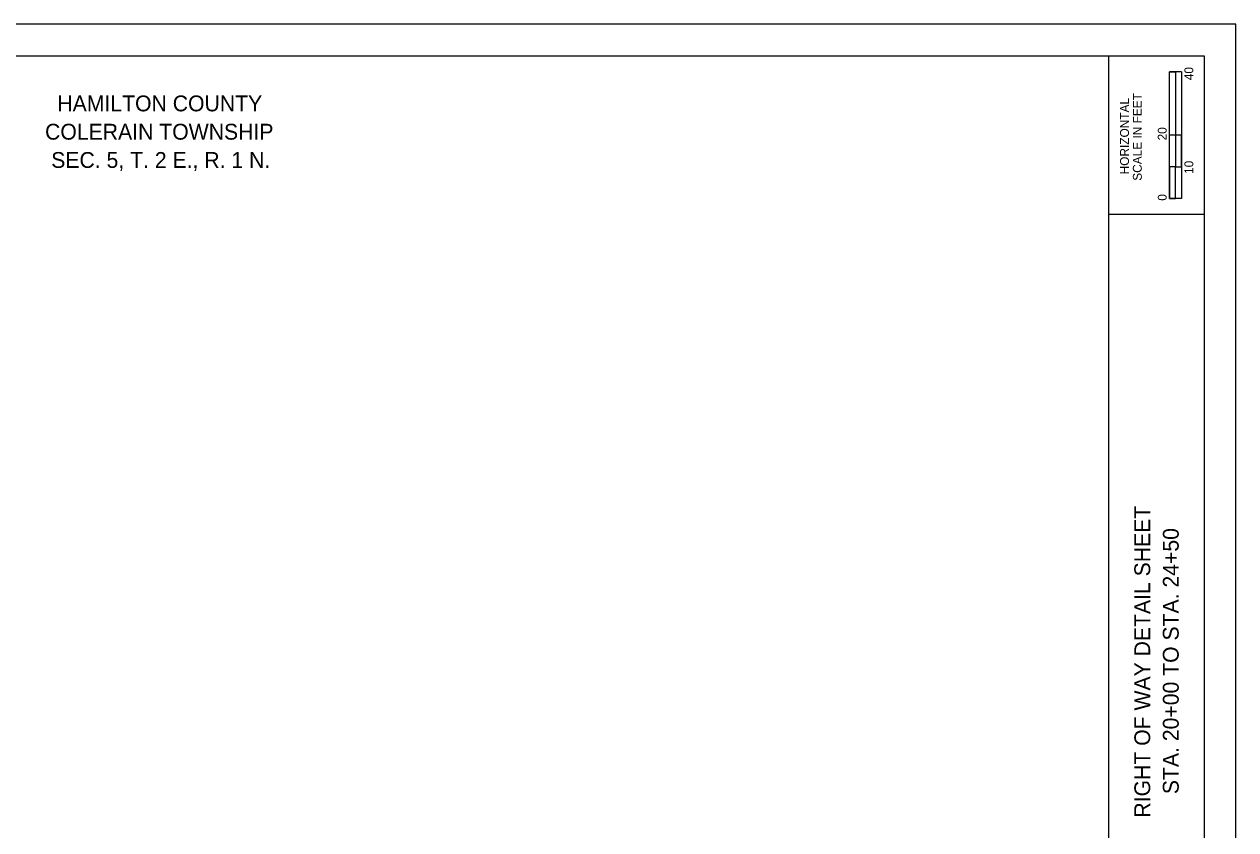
# Model space of a CAD drawing. Extents: x -0.5 to 34, y 0 to 22.
# Drawn here: x 14.89 to 34, y 9.28 to 22 of the extents above; entities that cross this region are included whole.
import ezdxf

# ---------------------------------------------------------------- set-up
doc = ezdxf.new("R2010")
doc.units = 0
for name, color, linetype in [('SH_Border', 7, 'Continuous'), ('SH_Cut_Line', 7, 'Continuous'), ('SH_Data', 7, 'Continuous')]:
    doc.layers.add(name, color=color, linetype=linetype)

msp = doc.modelspace()

# ---------------------------------------------------------------- linework, layer by layer
at = {"layer": 'SH_Border'}
for p, q in [((32, 0.5), (32, 21.5)), ((32, 19), (33.5, 19))]:
    msp.add_line(p, q, dxfattribs=at)
msp.add_lwpolyline([(1.5, 21.5), (33.5, 21.5), (33.5, 0.5), (1.5, 0.5)], close=True, dxfattribs=at)
at = {"layer": 'SH_Cut_Line'}
msp.add_lwpolyline([(0, 0), (34, 0), (34, 22), (0, 22)], close=True, dxfattribs=at)
at = {"layer": 'SH_Data'}
for p, q in [((32.957, 19.25), (32.957, 21.25)), ((33.144, 21.25), (32.957, 21.25)), ((32.957, 20.25), (32.957, 21.25)), ((32.957, 21.25), (33.05, 21.25)), ((33.05, 21.25), (33.051, 21.25)), ((33.051, 21.25), (33.051, 20.25)), ((33.144, 21.25), (33.144, 19.25)), ((33.051, 20.25), (32.957, 20.25)), ((33.143, 20.25), (33.05, 20.25)), ((33.05, 20.25), (33.05, 19.75)), ((33.143, 19.75), (33.143, 20.25)), ((33.05, 19.75), (32.957, 19.75)), ((32.957, 19.75), (32.957, 19.25)), ((33.05, 19.25), (33.05, 19.75)), ((33.05, 19.75), (33.143, 19.75)), ((33.144, 19.25), (32.957, 19.25)), ((32.957, 19.25), (33.05, 19.25))]:
    msp.add_line(p, q, dxfattribs=at)

# ---------------------------------------------------------------- texts
for s, height, p in [('40', 0.14, (33.33, 21.116)), ('SCALE IN FEET', 0.14, (32.517, 19.529)), ('HORIZONTAL', 0.14, (32.315, 19.63)), ('20', 0.14, (32.91, 20.166)), ('10', 0.14, (33.33, 19.637)), ('0', 0.14, (32.91, 19.214)), ('RIGHT OF WAY DETAIL SHEET', 0.25, (32.65, 9.477)), ('STA. 20+00 TO STA. 24+50', 0.25, (33.1, 9.847))]:
    msp.add_text(s, height=height, rotation=90, dxfattribs=at).set_placement(p)
for s, p in [('HAMILTON COUNTY', (15.41, 20.625)), ('COLERAIN TOWNSHIP', (15.216, 20.178)), ('SEC. 5, T. 2 E., R. 1 N.', (15.313, 19.732))]:
    msp.add_text(s, height=0.25, dxfattribs=at).set_placement(p)

doc.saveas('drawing.dxf')
